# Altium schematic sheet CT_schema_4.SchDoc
size 521 x 498 mm
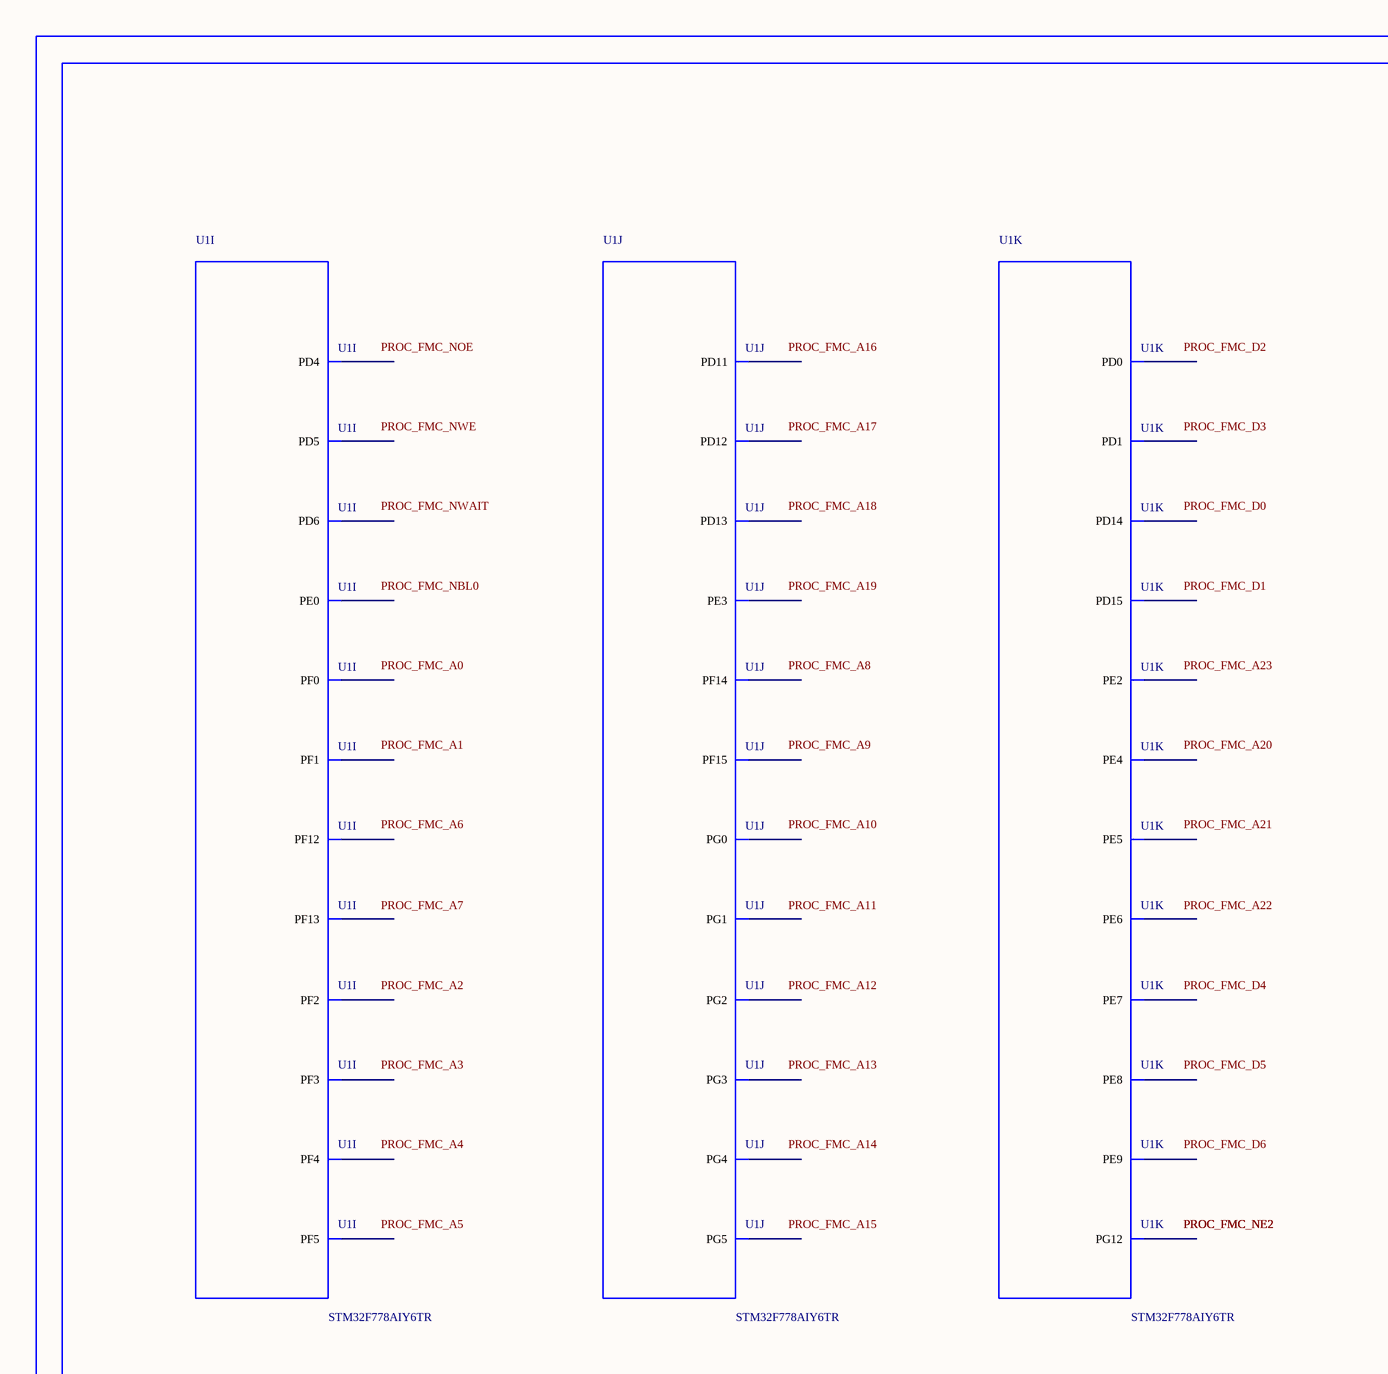
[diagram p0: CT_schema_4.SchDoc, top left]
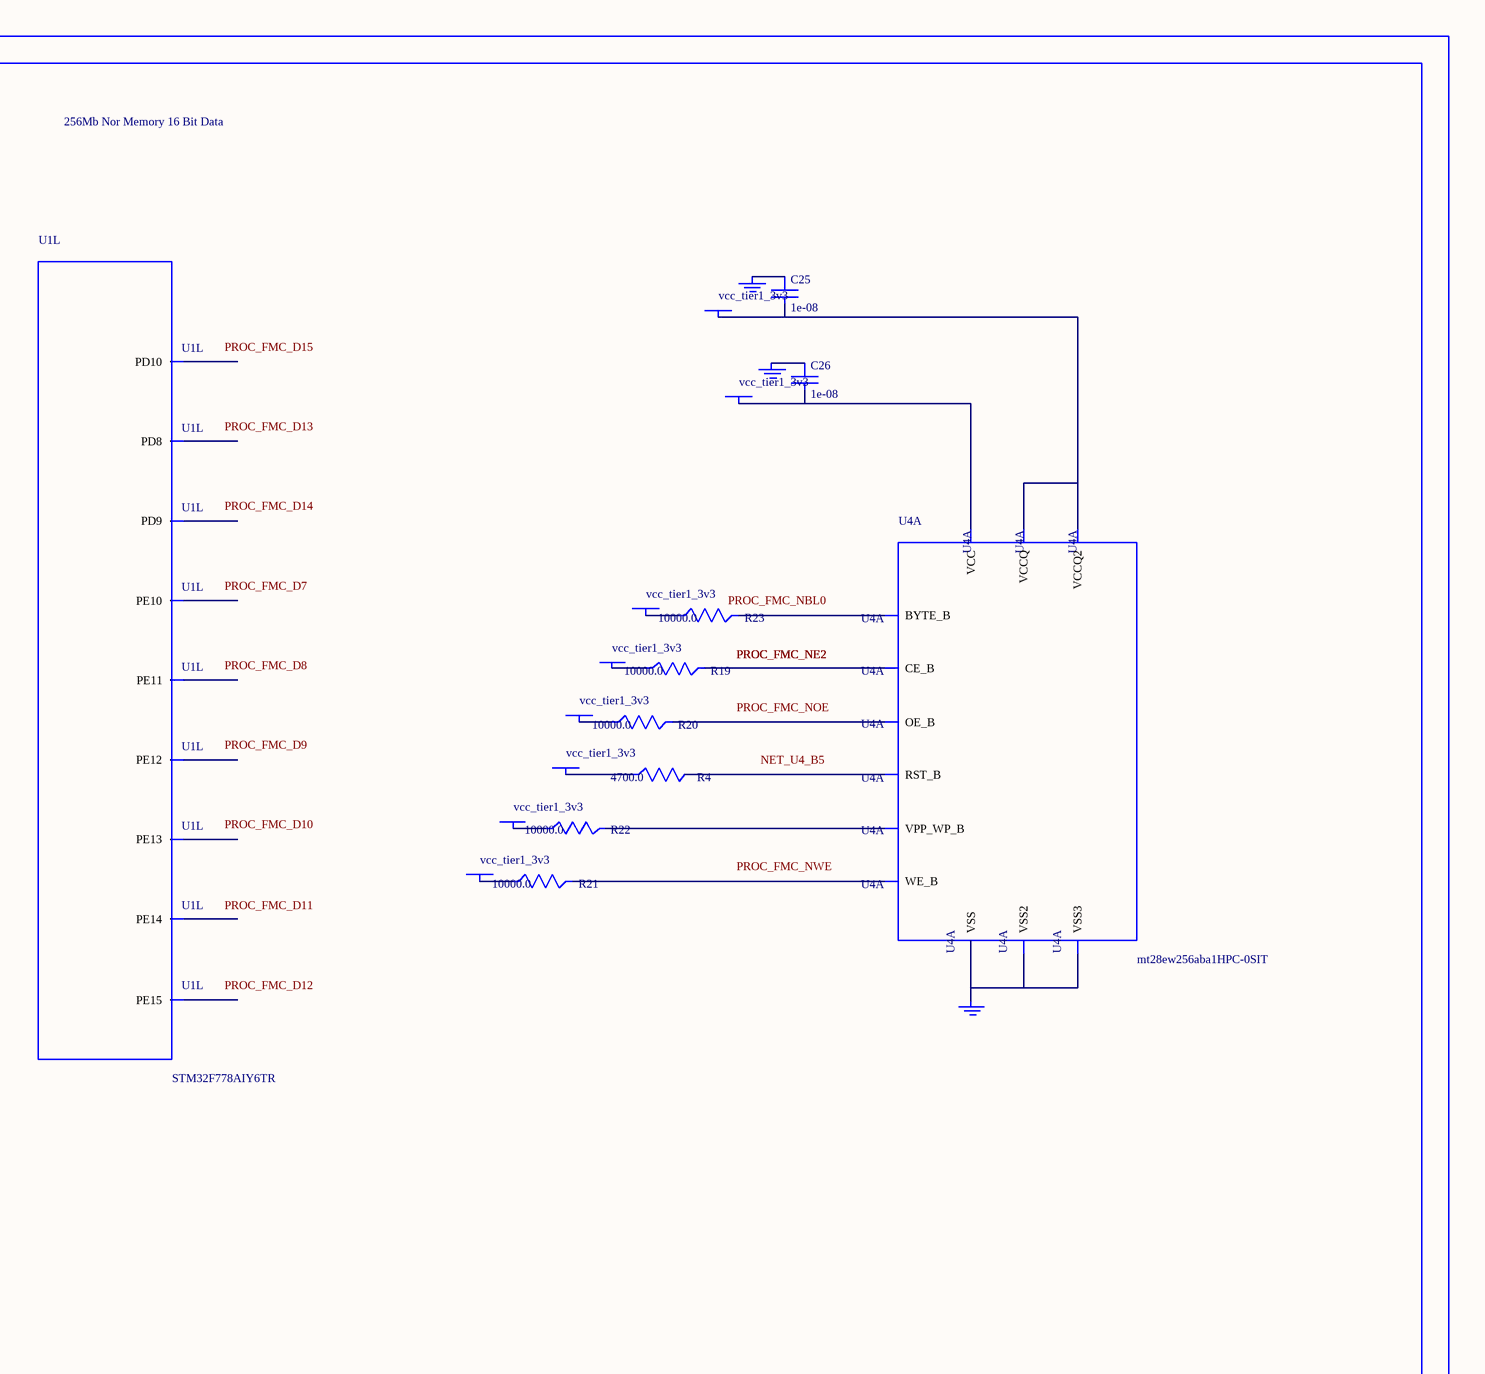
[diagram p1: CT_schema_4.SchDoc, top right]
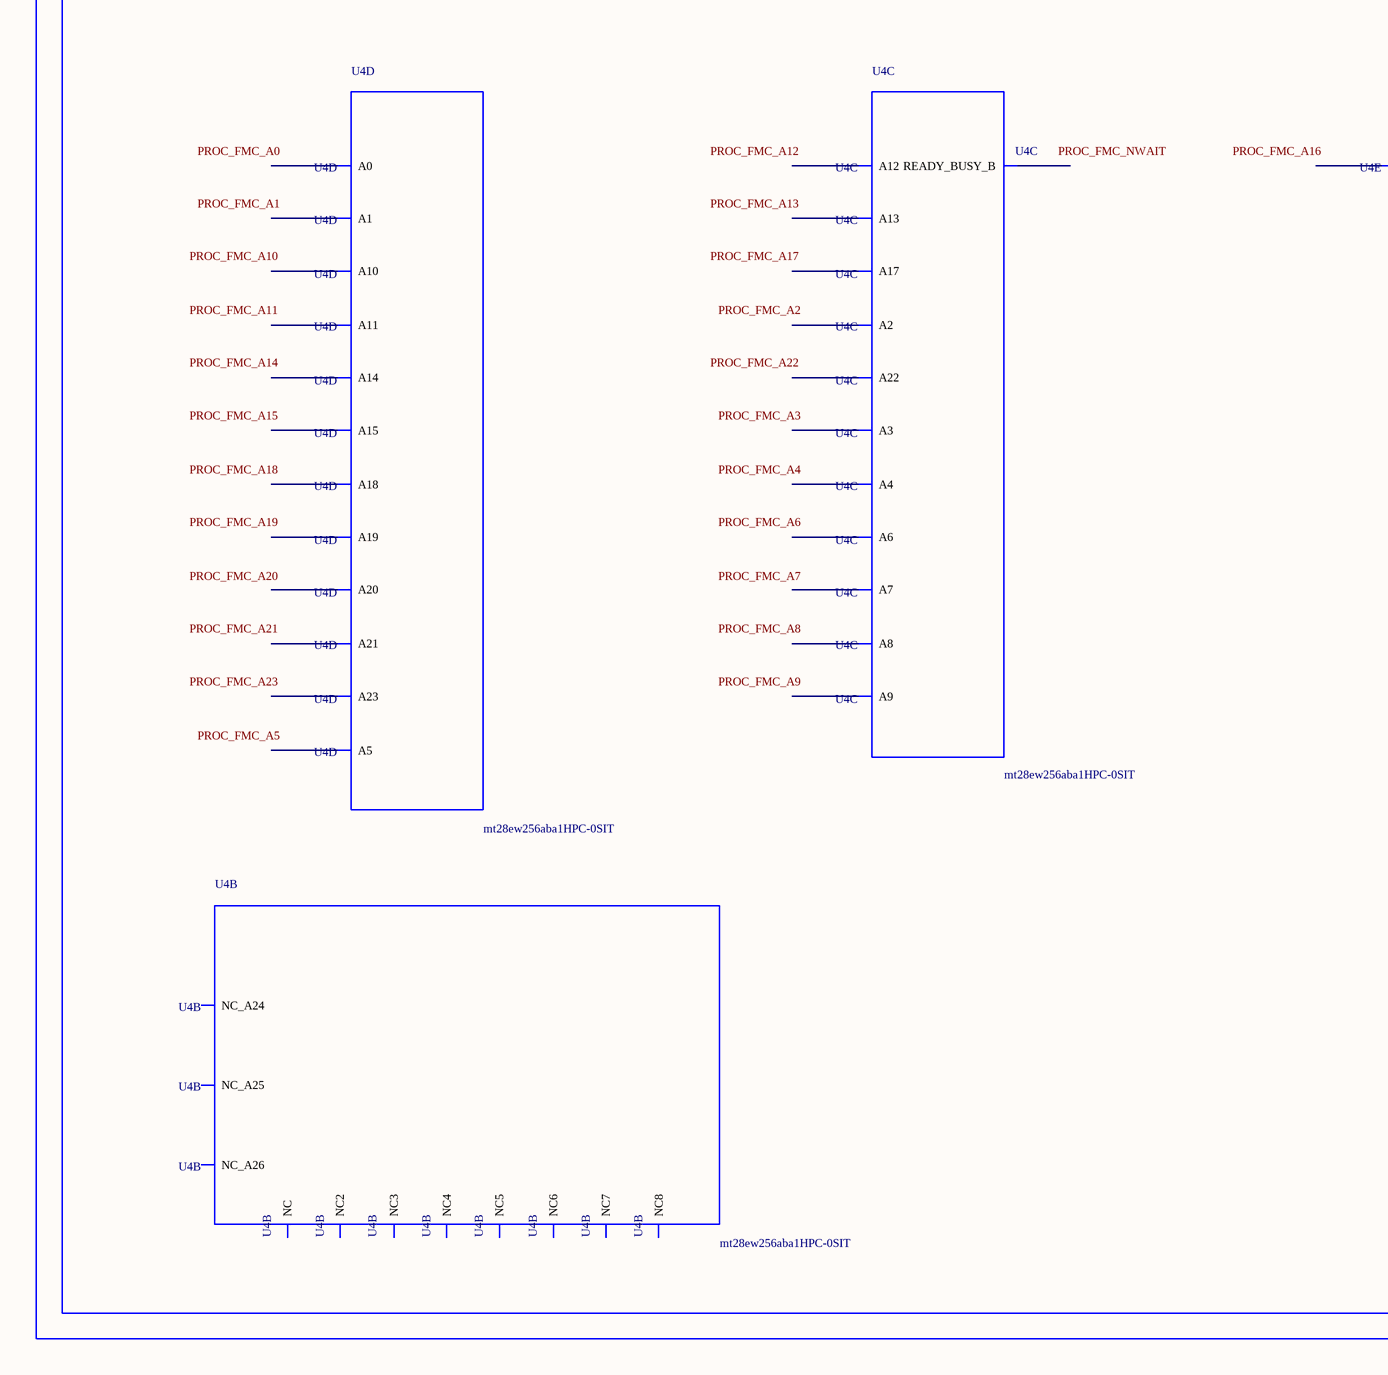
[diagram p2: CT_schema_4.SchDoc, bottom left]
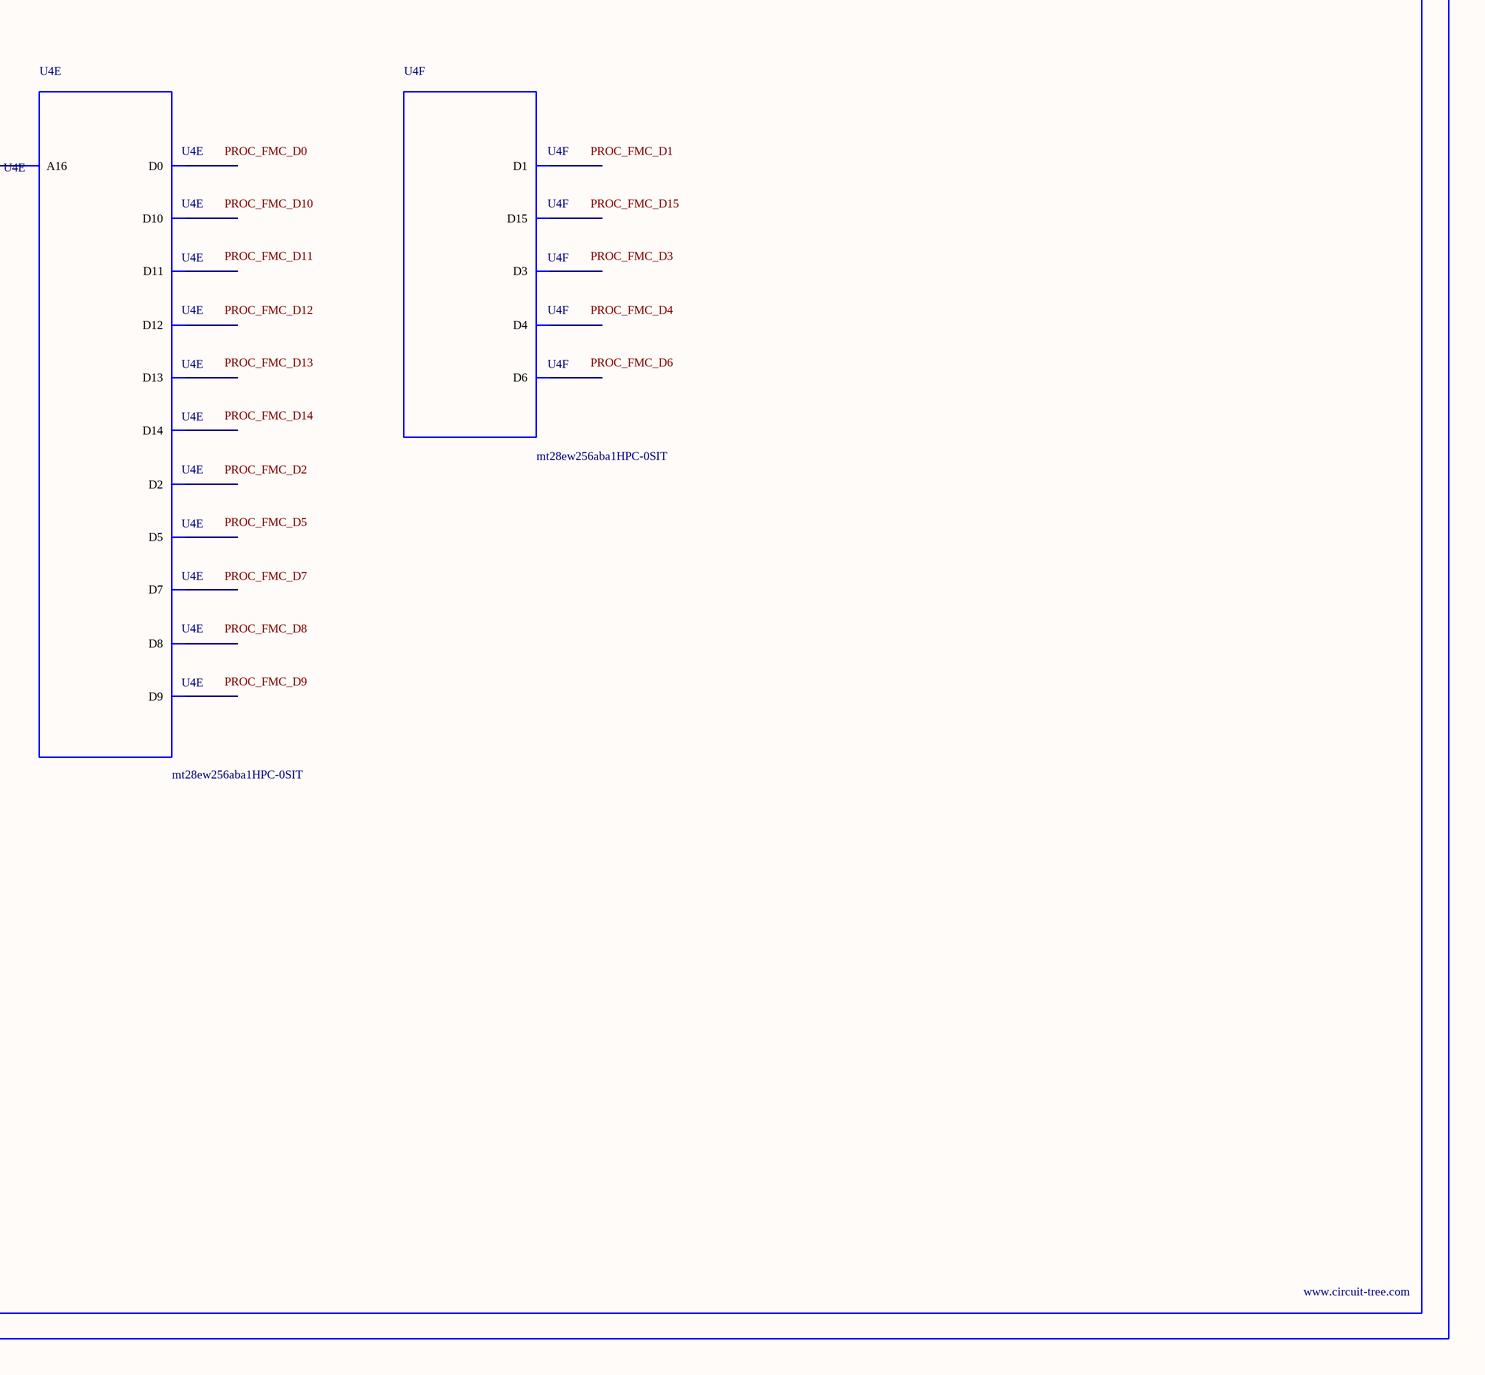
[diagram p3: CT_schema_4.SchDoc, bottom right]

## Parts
BORDER3  (no value)
C25  1e-08  [C0402]
C26  1e-08  [C0402]
GND_INSTANCE_3_0  (no value)
GND_INSTANCE_3_1  (no value)
GND_INSTANCE_3_2  (no value)
POWER_INSTANCE_3_0  vcc_tier1_3v3
POWER_INSTANCE_3_1  vcc_tier1_3v3
POWER_INSTANCE_3_2  vcc_tier1_3v3
POWER_INSTANCE_3_3  vcc_tier1_3v3
POWER_INSTANCE_3_4  vcc_tier1_3v3
POWER_INSTANCE_3_5  vcc_tier1_3v3
POWER_INSTANCE_3_6  vcc_tier1_3v3
POWER_INSTANCE_3_7  vcc_tier1_3v3
R4  4700.0  [R0603]
R19  10000.0  [R0603]
R20  10000.0  [R0603]
R21  10000.0  [R0603]
R22  10000.0  [R0603]
R23  10000.0  [R0603]
U1  STM32F778AIY6TR  [WLCSP180]  (parts I,J,K,L of 15)
U4  mt28ew256aba1HPC-0SIT  [LBGA-64]  (parts A,B,C,D,E,F of 6)

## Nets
NetC25_1: C25.1 GND_INSTANCE_3_0.0(GND)
NetC25_2: C25.2 POWER_INSTANCE_3_0.0(PWR) U4.D8(VCCQ) U4.F1(VCCQ2)
NetC26_1: C26.1 GND_INSTANCE_3_1.0(GND)
NetC26_2: C26.2 POWER_INSTANCE_3_1.0(PWR) U4.G5(VCC)
NetGND_INSTANCE_3_2_0: GND_INSTANCE_3_2.0(GND) U4.E8(VSS) U4.H2(VSS2) U4.H7(VSS3)
NetPOWER_INSTANCE_3_2_0: POWER_INSTANCE_3_2.0(PWR) R19.1
NetPOWER_INSTANCE_3_3_0: POWER_INSTANCE_3_3.0(PWR) R20.1
NetPOWER_INSTANCE_3_4_0: POWER_INSTANCE_3_4.0(PWR) R21.1
NetPOWER_INSTANCE_3_5_0: POWER_INSTANCE_3_5.0(PWR) R22.1
NetPOWER_INSTANCE_3_6_0: POWER_INSTANCE_3_6.0(PWR) R23.1
NetPOWER_INSTANCE_3_7_0: POWER_INSTANCE_3_7.0(PWR) R4.1
NetR4_2: R4.2 U4.B5(RST_B)
NetR19_2: R19.2 U4.F2(CE_B)
NetR20_2: R20.2 U4.G2(OE_B)
NetR21_2: R21.2 U4.A5(WE_B)
NetR22_2: R22.2 U4.B4(VPP_WP_B)
NetR23_2: R23.2 U4.F7(BYTE_B)

Not connected (* = marked no-connect by the designer): U1 A4(PD0) A5(PD4) C5(PD5) C9(PE0) C12(PE4) D5(PD1) D7(PG12) D12(PE5) E6(PD6) E10(PE2) E11(PE6) F10(PE3) G1(PG4) G2(PG5) G9(PG3) G11(PF0) G12(PF1) G13(PF2) H9(PG2) H11(PF3) H12(PF4) H13(PF5) J4(PD12) J6(PE10) K2(PD15) K3(PD11) K6(PE11) K7(PF12) K8(PF14) L1(PD14) L2(PD13) L3(PD9) L6(PE12) L7(PG1) L8(PF13) M2(PD10) M3(PD8) M6(PE15) M7(PE7) N6(PE14) N7(PE8) N8(PG0) P6(PE13) P7(PE9) P8(PF15); U4 A1(NC) A2(A3) A3(A7) A4(READY_BUSY_B) A6(A9) A7(A13) A8(NC2) B1(NC_A26) B2(A4) B3(A17) B6(A8) B7(A12) B8(A22) C1(NC3) C2(A2) C3(A6) C4(A18) C5(A21) C6(A10) C7(A14) C8(A23) D1(NC4) D2(A1) D3(A5) D4(A20) D5(A19) D6(A11) D7(A15) E1(NC5) E2(A0) E3(D0) E4(D2) E5(D5) E6(D7) E7(A16) F3(D8) F4(D10) F5(D12) F6(D14) F8(NC_A24) G1(NC6) G3(D9) G4(D11) G6(D13) G7(D15) G8(NC_A25) H1(NC7) H3(D1) H4(D3) H5(D4) H6(D6) H8(NC8)

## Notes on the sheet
- Labels drawn without touching a wire or pin: NET_U4_B5, PROC_FMC_A0, PROC_FMC_A1, PROC_FMC_A2, PROC_FMC_A3, PROC_FMC_A4, PROC_FMC_A5, PROC_FMC_A6, PROC_FMC_A7, PROC_FMC_A8, PROC_FMC_A9, PROC_FMC_A10, PROC_FMC_A11, PROC_FMC_A12, PROC_FMC_A13, PROC_FMC_A14, PROC_FMC_A15, PROC_FMC_A16, PROC_FMC_A17, PROC_FMC_A18, PROC_FMC_A19, PROC_FMC_A20, PROC_FMC_A21, PROC_FMC_A22, PROC_FMC_A23, PROC_FMC_D0, PROC_FMC_D1, PROC_FMC_D2, PROC_FMC_D3, PROC_FMC_D4, PROC_FMC_D5, PROC_FMC_D6, PROC_FMC_D7, PROC_FMC_D8, PROC_FMC_D9, PROC_FMC_D10, PROC_FMC_D11, PROC_FMC_D12, PROC_FMC_D13, PROC_FMC_D14, PROC_FMC_D15, PROC_FMC_NBL0, PROC_FMC_NOE, PROC_FMC_NWAIT, PROC_FMC_NWE

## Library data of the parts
BORDER3 = BORDER_PAGE3
C25 C26 = C0402C103K3RAC
GND_INSTANCE_3_0-GND_INSTANCE_3_2 = GND
POWER_INSTANCE_3_0-POWER_INSTANCE_3_7 = PWR
R4 = RC0603JR-074K7L
R19-R23 = RC0603JR-0710KL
